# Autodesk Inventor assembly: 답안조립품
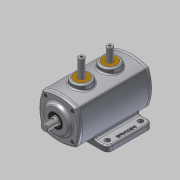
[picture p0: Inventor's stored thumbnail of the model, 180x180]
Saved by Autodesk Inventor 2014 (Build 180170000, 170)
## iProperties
Created: 2015-07
Part Number: 답안조립품
Document SubType Name: Assembly
Designer: Administrator
Mass: 2515.1 g
Surface Area: 1894.51 cm^2
Volume: 719.238 cm^3
Density: 3.4969 g/cm^3
Author: Administrator
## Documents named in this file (12)
- C:\Users\Administrator\Desktop\350727V1010\답안조립품.iam
- C:\Users\Administrator\Desktop\350727V1010\본체.ipt
- C:\Users\Administrator\Desktop\350727V1010\뒷커버.ipt
- C:\Users\Administrator\Desktop\350727V1010\베어링 6203.ipt
- C:\Users\Administrator\Desktop\350727V1010\M4-소켓머리.ipt
- C:\Users\Administrator\Desktop\350727V1010\축.ipt
- C:\Users\Administrator\Desktop\350727V1010\앞커버.ipt
- C:\Users\Administrator\Desktop\350727V1010\오일실.ipt
- C:\Users\Administrator\Desktop\350727V1010\슬라이더.ipt
- C:\Users\Administrator\Desktop\350727V1010\스프링_01.ipt
- C:\Users\Administrator\Desktop\350727V1010\스프링_02.ipt
- C:\Users\Administrator\Desktop\350727V1010\부시.ipt
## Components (11 placed, 3 different names)
1. 7-베어링 6203:1 — 각도:1
2. 9-M4-소켓머리:1
3. 9-M4-소켓머리:2
4. 9-M4-소켓머리:3
5. 9-M4-소켓머리:4
6. 7-베어링 6203:2 — 각도:2
7. 9-M4-소켓머리:5
8. 9-M4-소켓머리:6
9. 9-M4-소켓머리:7
10. 9-M4-소켓머리:8
11. 8-오일실:1
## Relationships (2: Angle 2)
- 각도:1 [Angle]: 7-베어링 6203:1
- 각도:2 [Angle]: 7-베어링 6203:2
